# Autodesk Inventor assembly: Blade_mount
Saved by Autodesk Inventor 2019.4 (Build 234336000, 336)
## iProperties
Created: 2020-02
Part Number: Blade_mount
Document SubType Name: Assembly
Designer: Administrator
Title: Blade_mount v18
Author: Administrator
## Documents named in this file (10)
- c:\worker\convert-fusion-r01\tmp\job-1\5\output\files\e4333473-a38b-4431-9958-ad24a2f67704\Blade_mount v18.iam
- c:\worker\convert-fusion-r01\tmp\job-1\5\output\files\e4333473-a38b-4431-9958-ad24a2f67704\Component1.ipt
- c:\worker\convert-fusion-r01\tmp\job-1\5\output\files\e4333473-a38b-4431-9958-ad24a2f67704\Component2.ipt
- c:\worker\convert-fusion-r01\tmp\job-1\5\output\files\e4333473-a38b-4431-9958-ad24a2f67704\Component3.ipt
- c:\worker\convert-fusion-r01\tmp\job-1\5\output\files\e4333473-a38b-4431-9958-ad24a2f67704\Component4.ipt
- c:\worker\convert-fusion-r01\tmp\job-1\5\output\files\e4333473-a38b-4431-9958-ad24a2f67704\Component5.ipt
- c:\worker\convert-fusion-r01\tmp\job-1\5\output\files\e4333473-a38b-4431-9958-ad24a2f67704\Component6.ipt
- c:\worker\convert-fusion-r01\tmp\job-1\5\output\files\e4333473-a38b-4431-9958-ad24a2f67704\Component7.ipt
- c:\worker\convert-fusion-r01\tmp\job-1\5\output\files\e4333473-a38b-4431-9958-ad24a2f67704\Component8.ipt
- c:\worker\convert-fusion-r01\tmp\job-1\5\output\files\e4333473-a38b-4431-9958-ad24a2f67704\Component9.ipt
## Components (9 placed, 9 different names)
1. Component1:1
2. Component2:1
3. Component3:1
4. Component4:1
5. Component5:1
6. Component6:1
7. Component7:1
8. Component8:1
9. Component9:1
